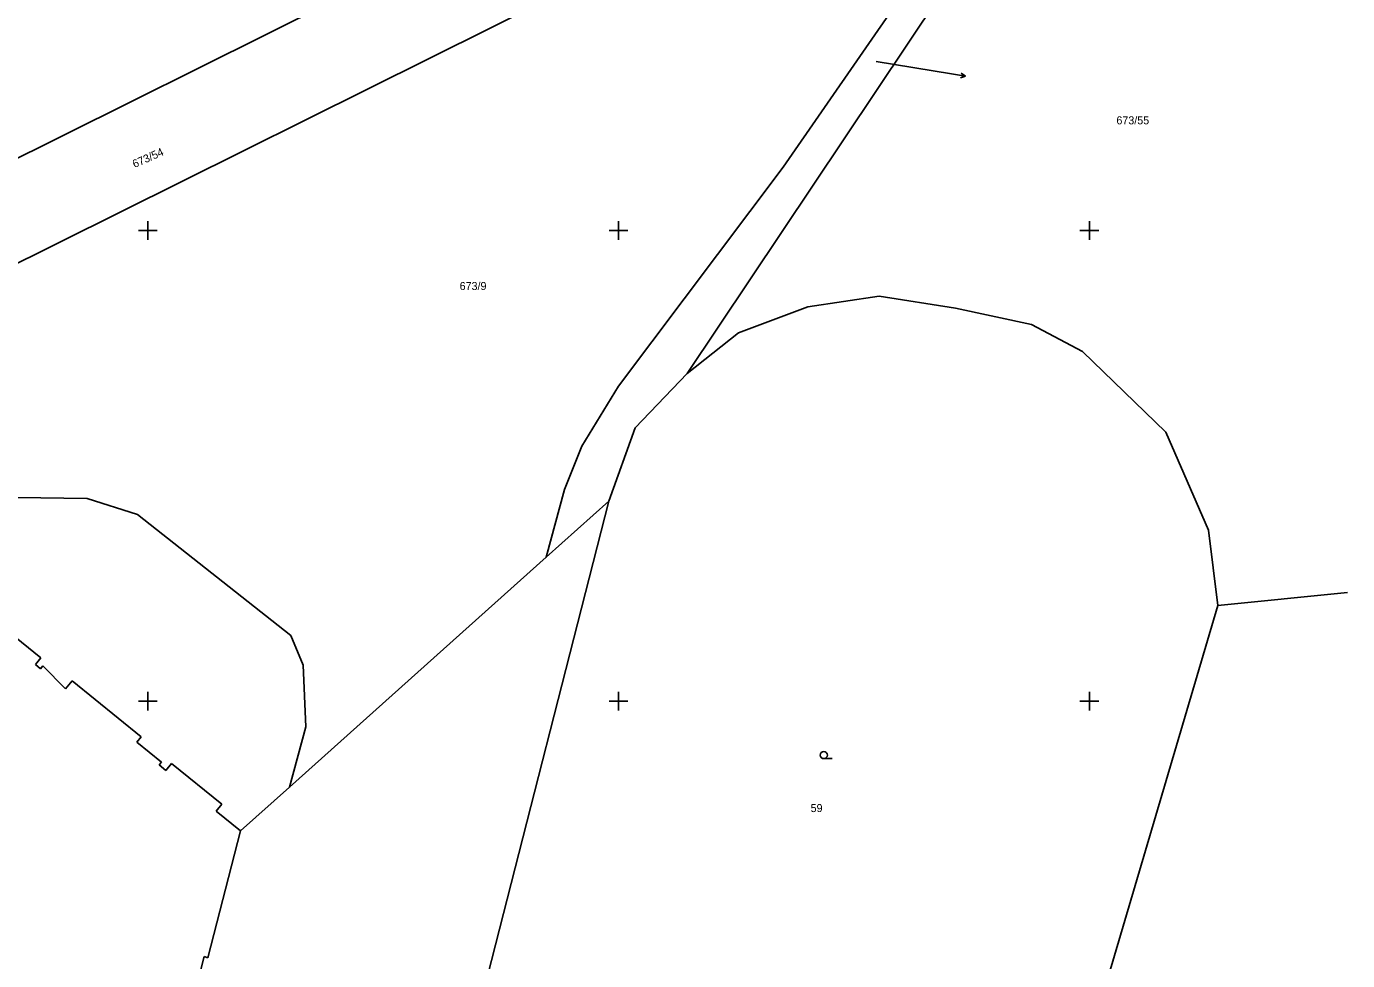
# Model space of a CAD drawing. Extents: x -492811 to -492366, y -1127107 to -1126748.
# Drawn here: x -492485.2 to -492429, y -1126951 to -1126911.3 of the extents above; entities that cross this region are included whole.
import ezdxf

# ---------------------------------------------------------------- set-up
doc = ezdxf.new("R2010")
doc.units = 0
doc.layers.add('katastrální mapa', color=7, linetype='Continuous')
doc.layers.add('síť', color=7, linetype='Continuous')

msp = doc.modelspace()

# ---------------------------------------------------------------- linework, layer by layer
at = {"layer": 'katastrální mapa'}
for p, q in [((-492457.09, -1126926.08), (-492439.32, -1126899.52)), ((-492458.35, -1126907.86), (-492531.1, -1126944.05)), ((-492446.69, -1126908.18), (-492453.01, -1126917.31)), ((-492487.04, -1126917.67), (-492472.13, -1126910.26)), ((-492449.05, -1126912.82), (-492445.85, -1126913.35)), ((-492445.85, -1126913.35), (-492445.26, -1126913.45)), ((-492445.26, -1126913.45), (-492445.47, -1126913.51)), ((-492445.26, -1126913.45), (-492445.44, -1126913.32)), ((-492453.01, -1126917.31), (-492460, -1126926.61)), ((-492451.96, -1126923.25), (-492448.93, -1126922.79)), ((-492448.93, -1126922.79), (-492445.69, -1126923.3)), ((-492454.91, -1126924.35), (-492451.96, -1126923.25)), ((-492445.69, -1126923.3), (-492442.46, -1126923.99)), ((-492442.46, -1126923.99), (-492440.29, -1126925.14)), ((-492457.09, -1126926.08), (-492454.91, -1126924.35)), ((-492440.29, -1126925.14), (-492436.75, -1126928.57)), ((-492459.3, -1126928.38), (-492457.09, -1126926.08)), ((-492460, -1126926.61), (-492461.56, -1126929.17)), ((-492460.41, -1126931.5), (-492459.3, -1126928.38)), ((-492436.75, -1126928.57), (-492434.94, -1126932.73)), ((-492461.56, -1126929.17), (-492462.3, -1126931)), ((-492462.3, -1126931), (-492463.07, -1126933.88)), ((-492485.54, -1126931.34), (-492482.58, -1126931.39)), ((-492482.58, -1126931.39), (-492480.43, -1126932.07)), ((-492468.09, -1126961.52), (-492460.41, -1126931.5)), ((-492460.41, -1126931.5), (-492463.07, -1126933.88)), ((-492480.43, -1126932.07), (-492473.92, -1126937.21)), ((-492434.94, -1126932.73), (-492434.54, -1126935.94)), ((-492463.07, -1126933.88), (-492473.98, -1126943.65)), ((-492434.54, -1126935.94), (-492429.03, -1126935.38)), ((-492443.9, -1126967.57), (-492434.54, -1126935.94)), ((-492486.75, -1126936.37), (-492484.54, -1126938.15)), ((-492473.92, -1126937.21), (-492473.4, -1126938.47)), ((-492484.77, -1126938.44), (-492484.54, -1126938.15)), ((-492484.77, -1126938.44), (-492484.56, -1126938.62)), ((-492484.56, -1126938.62), (-492484.46, -1126938.5)), ((-492484.46, -1126938.5), (-492483.49, -1126939.48)), ((-492473.4, -1126938.47), (-492473.28, -1126941.09)), ((-492483.49, -1126939.48), (-492483.21, -1126939.13)), ((-492483.21, -1126939.13), (-492480.28, -1126941.51)), ((-492473.98, -1126943.65), (-492473.28, -1126941.09)), ((-492480.47, -1126941.74), (-492480.28, -1126941.51)), ((-492480.47, -1126941.74), (-492479.42, -1126942.59)), ((-492479.52, -1126942.7), (-492479.42, -1126942.59)), ((-492479.52, -1126942.7), (-492479.23, -1126942.94)), ((-492479.23, -1126942.94), (-492478.99, -1126942.64)), ((-492478.99, -1126942.64), (-492476.86, -1126944.38)), ((-492451.28, -1126942.44), (-492450.93, -1126942.44)), ((-492473.98, -1126943.65), (-492476.06, -1126945.51)), ((-492477.09, -1126944.67), (-492476.86, -1126944.38)), ((-492477.09, -1126944.67), (-492476.06, -1126945.51)), ((-492477.45, -1126950.9), (-492476.06, -1126945.51)), ((-492479.65, -1126958.85), (-492477.61, -1126950.85)), ((-492477.61, -1126950.85), (-492477.45, -1126950.9))]:
    msp.add_line(p, q, dxfattribs=at)
msp.add_circle((-492451.28, -1126942.29), 0.15, dxfattribs=at)
at = {"layer": 'síť'}
for p, q in [((-492480, -1126919.6), (-492480, -1126920.4)), ((-492460, -1126919.6), (-492460, -1126920.4)), ((-492440, -1126919.6), (-492440, -1126920.4)), ((-492480.4, -1126920), (-492479.6, -1126920)), ((-492460.4, -1126920), (-492459.6, -1126920)), ((-492440.4, -1126920), (-492439.6, -1126920)), ((-492480.4, -1126940), (-492479.6, -1126940)), ((-492480, -1126939.6), (-492480, -1126940.4)), ((-492460.4, -1126940), (-492459.6, -1126940)), ((-492460, -1126939.6), (-492460, -1126940.4)), ((-492440.4, -1126940), (-492439.6, -1126940)), ((-492440, -1126939.6), (-492440, -1126940.4))]:
    msp.add_line(p, q, dxfattribs=at)

# ---------------------------------------------------------------- texts
at = {"layer": 'katastrální mapa'}
for s, height, p in [('673/55', 0.02, (-492449.1, -1126912.82)), ('673/55', 0.34, (-492438.85, -1126915.49)), ('673/9', 0.34, (-492466.75, -1126922.53)), ('59', 0.34, (-492451.84, -1126944.71))]:
    msp.add_text(s, height=height, dxfattribs=at).set_placement(p)
msp.add_text('673/54', height=0.34, rotation=24.0264, dxfattribs=at).set_placement((-492480.56, -1126917.35))

doc.saveas('drawing.dxf')
